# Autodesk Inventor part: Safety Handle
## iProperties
Created: 2002-02
Part Number: Safety Handle
Document SubType Name: Modeling
Designer: ***
Control State: 0
Master: False
Checked Out: False
Shininess: 77.0
Length Units: 11269
Angle Units: 11279
Time Units: 11290
Mass Units: 11283
Length Display Precision: 3
Angle Display Precision: 2
Density: 0.0
Volumn: 0.0
Area: 0.0
PropertySet Name: Model Information
Author: ***
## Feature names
1. Revolution1
2. Revolution2
